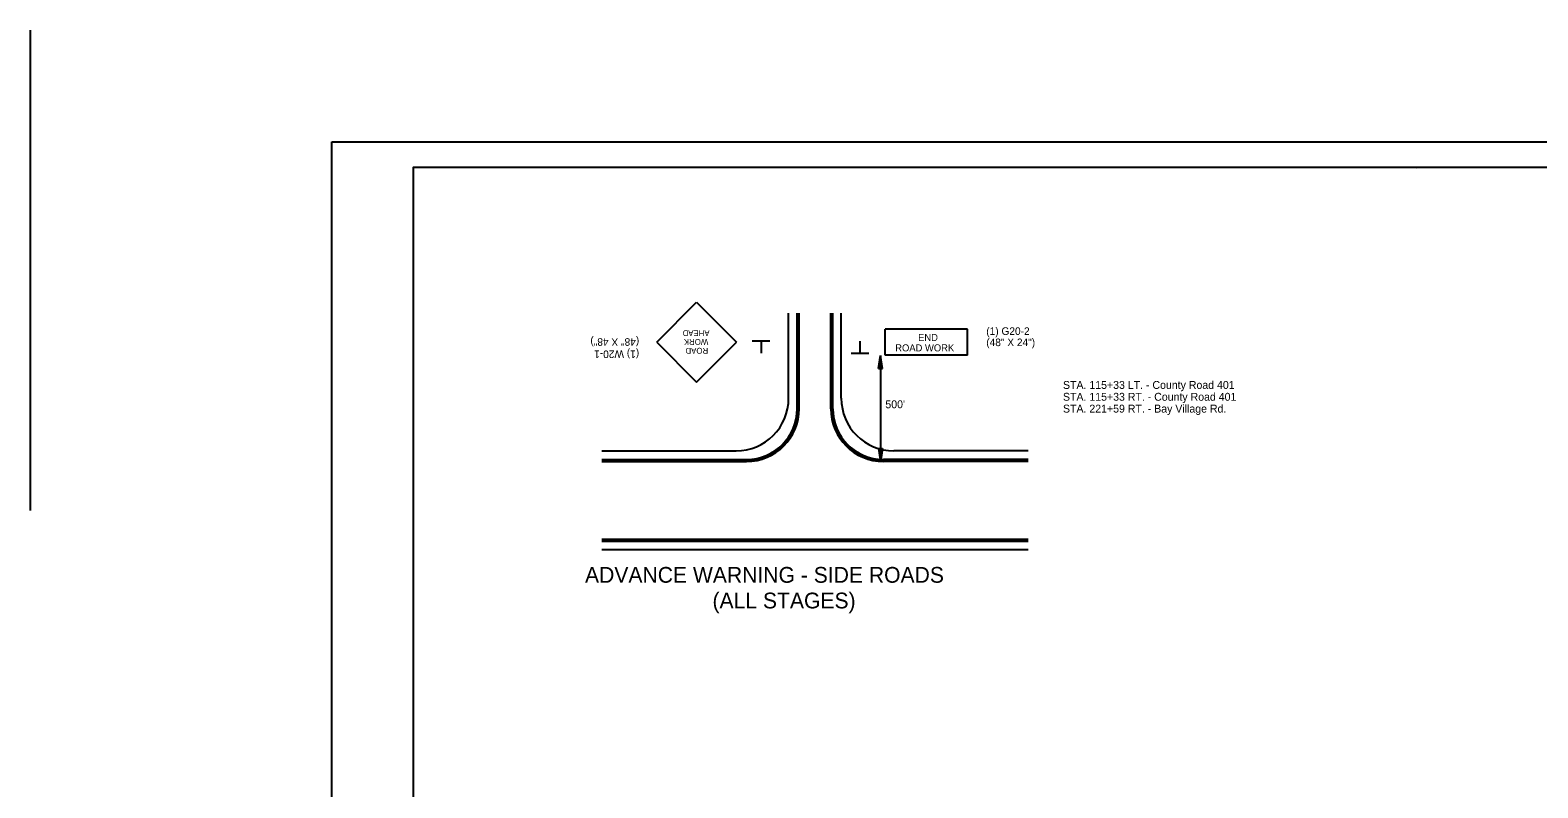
# Model space of a CAD drawing. Extents: x 1678017 to 1687792, y 404433 to 413488.
# Drawn here: x 1679525 to 1680671, y 411265 to 411841 of the extents above; entities that cross this region are included whole.
import ezdxf

# ---------------------------------------------------------------- set-up
doc = ezdxf.new("R2010")
doc.units = 0
for name, color, linetype in [('Default', 7, 'Continuous'), ('S_BUILDING', 7, 'Continuous'), ('S_GRAVEL_ROAD', 7, 'Continuous'), ('S_STREAM', 7, 'Continuous'), ('S_TELEPHONE_UTILITIES', 7, 'Continuous'), ('S_WATER_UTILITIES', 7, 'Continuous')]:
    doc.layers.add(name, color=color, linetype=linetype)

# ---------------------------------------------------------------- blocks, each defined once
blk = doc.blocks.new('SY')
at = {"layer": 'S_GRAVEL_ROAD'}
for p, q in [((-11.194, 0.328), (11.306, 0.328)), ((0, 0), (0, -15.357))]:
    blk.add_line(p, q, dxfattribs=at)

msp = doc.modelspace()

# ---------------------------------------------------------------- linework, layer by layer
at = {"layer": 'Default'}
for p, q in [((1679524.8, 411840.9), (1679524.8, 411475.9)), ((1680001, 411603.8), (1680031.3, 411634.1)), ((1680031.3, 411634.1), (1680061.6, 411603.8)), ((1680109.3, 411553.2), (1680109.3, 411625.9)), ((1680133.3, 411553.2), (1680133.3, 411625.9)), ((1680237.3, 411613.7), (1680174.7, 411613.7)), ((1680174.7, 411594), (1680174.7, 411613.7)), ((1680237.3, 411594), (1680237.3, 411613.7)), ((1680001, 411603.8), (1680031.3, 411573.5)), ((1680031.3, 411573.5), (1680061.6, 411603.8)), ((1680237.3, 411594), (1680174.7, 411594)), ((1679959.3, 411513.2), (1680069.3, 411513.2)), ((1680283.3, 411513.2), (1680173.3, 411513.2)), ((1679959.3, 411454.2), (1680283.3, 411454.2))]:
    msp.add_line(p, q, dxfattribs=at)
for centre, start, end in [((1680069.3, 411553.2), 270, 0), ((1680173.3, 411553.2), 180, 270)]:
    msp.add_arc(centre, 40, start, end, dxfattribs=at)
at = {"layer": 'S_BUILDING'}
for p, q in [((1679816.2, 411736.7), (1681397.1, 411736.7)), ((1679816.2, 410709.4), (1679816.2, 411736.7)), ((1680578.8, 411735.4), (1680578.8, 411735.4)), ((1680578.8, 411735.4), (1680578.8, 411735.4))]:
    msp.add_line(p, q, dxfattribs=at)
at = {"layer": 'S_STREAM'}
for p, q in [((1679754.2, 411756.1), (1681420.8, 411756.1)), ((1680101.3, 411561.2), (1680101.3, 411625.9)), ((1680141.3, 411561.2), (1680141.3, 411625.9)), ((1679959.3, 411521.2), (1680061.3, 411521.2)), ((1680283.3, 411521.2), (1680181.3, 411521.2)), ((1679959.3, 411446.2), (1680283.3, 411446.2))]:
    msp.add_line(p, q, dxfattribs=at)
for points in [[(1679754.1, 411756.1), (1681420.8, 411756.1), (1681420.8, 410689.5), (1679754.1, 410689.5)], [(1680985.8, 411736.7), (1681083.9, 411736.7), (1681083.9, 411687.3), (1681164.4, 411687.3), (1681280.4, 411687.3), (1681280.4, 411565.6), (1681397.1, 411565.6), (1681397.1, 410709.4), (1679816.2, 410709.4), (1679816.2, 411736.7)]]:
    msp.add_lwpolyline(points, close=True, dxfattribs=at)
for centre, start, end in [((1680061.3, 411561.2), 270, 0), ((1680181.3, 411561.2), 180, 270)]:
    msp.add_arc(centre, 40, start, end, dxfattribs=at)
at = {"layer": 'S_TELEPHONE_UTILITIES'}
for p, q in [((1680169.5, 411583.8), (1680171, 411593.8)), ((1680171, 411593.8), (1680171, 411513)), ((1680172.5, 411583.8), (1680171, 411593.8)), ((1680169.5, 411583.8), (1680172.5, 411583.8)), ((1680169.7, 411583.8), (1680171, 411592.1)), ((1680170, 411583.8), (1680171, 411590.4)), ((1680170.3, 411583.8), (1680171, 411588.7)), ((1680170.5, 411583.8), (1680171, 411587)), ((1680170.8, 411583.8), (1680171, 411585.4)), ((1680172.2, 411583.8), (1680171, 411592.1)), ((1680172, 411583.8), (1680171, 411590.4)), ((1680171.7, 411583.8), (1680171, 411588.7)), ((1680171.5, 411583.8), (1680171, 411587)), ((1680171.2, 411583.8), (1680171, 411585.4)), ((1680169.5, 411523), (1680171, 411513)), ((1680169.5, 411523), (1680172.5, 411523)), ((1680169.7, 411523), (1680171, 411514.7)), ((1680170, 411523), (1680171, 411516.4)), ((1680170.3, 411523), (1680171, 411518.1)), ((1680170.5, 411523), (1680171, 411519.7)), ((1680170.8, 411523), (1680171, 411521.4)), ((1680172.5, 411523), (1680171, 411513)), ((1680171.5, 411523), (1680171, 411519.7)), ((1680172, 411523), (1680171, 411516.4)), ((1680172.2, 411523), (1680171, 411514.7)), ((1680171.7, 411523), (1680171, 411518.1)), ((1680171.2, 411523), (1680171, 411521.4))]:
    msp.add_line(p, q, dxfattribs=at)
at = {"layer": 'S_WATER_UTILITIES'}
for p, q in [((1680107.8, 411553.2), (1680107.8, 411625.9)), ((1680108.3, 411553.2), (1680108.3, 411625.9)), ((1680134.3, 411553.2), (1680134.3, 411625.9)), ((1680134.8, 411553.2), (1680134.8, 411625.9)), ((1679959.3, 411514.7), (1680069.3, 411514.7)), ((1679959.3, 411514.2), (1680069.3, 411514.2)), ((1680283.3, 411514.7), (1680173.3, 411514.7)), ((1680283.3, 411514.2), (1680173.3, 411514.2)), ((1679959.3, 411453.2), (1680283.3, 411453.2)), ((1679959.3, 411452.7), (1680283.3, 411452.7))]:
    msp.add_line(p, q, dxfattribs=at)
for centre, radius, start, end in [((1680069.3, 411553.2), 39, 270, 0), ((1680069.3, 411553.2), 38.5, 270, 0), ((1680173.3, 411553.2), 39, 180, 270), ((1680173.3, 411553.2), 38.5, 180, 270)]:
    msp.add_arc(centre, radius, start, end, dxfattribs=at)

# ---------------------------------------------------------------- block references
at = {"layer": 'Default', "xscale": 0.6, "yscale": 0.6}
msp.add_blockref('SY', (1680080.3, 411604.6), dxfattribs=at)
at = {"layer": 'Default', "xscale": 0.6, "yscale": 0.6, "rotation": 180}
msp.add_blockref('SY', (1680155.6, 411595.3), dxfattribs=at)

# ---------------------------------------------------------------- texts
at = {"layer": 'Default'}
for s, height, rotation, p in [('(1) G20-2', 5.76, 0.0214, (1680251.5, 411609.3)), ('(48" X 48")', 5.757, 180.0165, (1679987.7, 411606.8)), ('AHEAD', 4.46, 180.017, (1680041.2, 411612.9)), ('WORK', 4.46, 180.0165, (1680040.2, 411606.2)), ('END', 5.34, 0.0214, (1680199.7, 411604.7)), ('(48" X 24")', 5.757, 0.0214, (1680251.5, 411600.8)), ('(1) W20-1', 5.76, 180.0165, (1679987.7, 411597.5)), ('ROAD', 4.46, 180.0169, (1680040.1, 411599.5)), ('ROAD WORK', 5.34, 0.0214, (1680182.3, 411596.8))]:
    msp.add_text(s, height=height, rotation=rotation, dxfattribs=at).set_placement(p)
for s, height, p in [('STA. 115+33 LT. - County Road 401', 6, (1680309.8, 411568.3)), ('STA. 115+33 RT. - County Road 401', 6, (1680309.8, 411559.3)), ('STA. 221+59 RT. - Bay Village Rd.', 6, (1680309.8, 411550.3)), ('ADVANCE WARNING - SIDE ROADS', 12, (1679946.5, 411421)), ('(ALL STAGES)', 12, (1680043.4, 411401.5))]:
    msp.add_text(s, height=height, dxfattribs=at).set_placement(p)
at = {"layer": 'S_TELEPHONE_UTILITIES'}
msp.add_text("500'", height=6, dxfattribs=at).set_placement((1680174.8, 411553.6))

doc.saveas('drawing.dxf')
